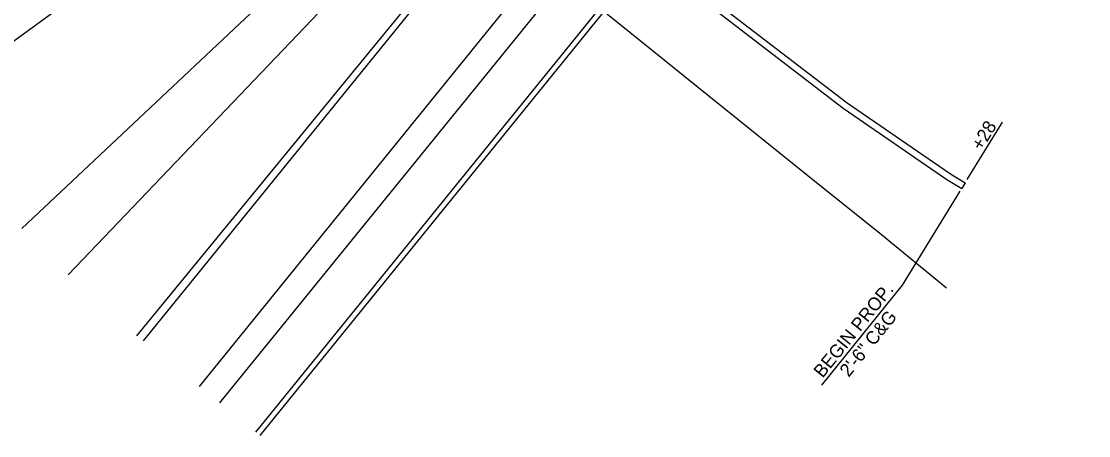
# Model space of a CAD drawing. Extents: x 1486489 to 1490134, y 497089 to 500876.
# Drawn here: x 1488844.3 to 1489168.8, y 498888.9 to 499014.9 of the extents above; entities that cross this region are included whole.
import ezdxf

# ---------------------------------------------------------------- set-up
doc = ezdxf.new("R2010")
doc.units = 0
for name, color, linetype in [('Old_Level_9', 7, 'Continuous'), ('Prop Text', 7, 'Continuous'), ('Scratch_Level_5', 7, 'Continuous'), ('Sheet Border Standard 30in CELL', 7, 'Continuous'), ('Sheet Cutting Line CELL', 7, 'Continuous'), ('Sheet Sticker Exception Certification CELL', 7, 'Continuous')]:
    doc.layers.add(name, color=color, linetype=linetype)

msp = doc.modelspace()

# ---------------------------------------------------------------- linework, layer by layer
at = {"layer": 'Old_Level_9'}
msp.add_lwpolyline([(1489125.56, 498933.79), (1489105.79, 498950), (1489083.46, 498967.96), (1489053.28, 498992.22), (1489018.86, 499019.95), (1488995.28, 499038.96), (1488972.75, 499057.15), (1488947.35, 499077.62), (1488919.48, 499100.08), (1488890.07, 499123.82), (1488841.68, 499162.79)], dxfattribs=at)
at = {"layer": 'Prop Text'}
for p, q in [((1489133.24, 499228.47), (1488881.33, 498917.76)), ((1488858.52, 498937.81), (1489134.65, 499227.2)), ((1489156.48, 499209.63), (1488904.57, 498898.92)), ((1489167.42, 499200.76), (1488915.51, 498890.05)), ((1488916.88, 498888.94), (1489168.79, 499199.65))]:
    msp.add_line(p, q, dxfattribs=at)
msp.add_lwpolyline([(1488898.42, 498903.91), (1488898.42, 498903.91), (1489150.33, 499214.62)], dxfattribs=at)
at = {"layer": 'Scratch_Level_5'}
msp.add_line((1489131.27, 498965.85), (1489130.23, 498964.14), dxfattribs=at)
msp.add_lwpolyline([(1489042.71, 499028.27), (1489054.46, 499018.99), (1489094.18, 498988.49), (1489125.68, 498966.85), (1489130.23, 498964.14)], dxfattribs=at)
at = {"layer": 'Sheet Border Standard 30in CELL'}
for p, q in [((1488879.44, 498919.3), (1489132.96, 499228.7)), ((1489135.79, 499226.06), (1488844.47, 498951.95)), ((1488814, 498988.85), (1489138.26, 499223.06))]:
    msp.add_line(p, q, dxfattribs=at)
at = {"layer": 'Sheet Cutting Line CELL'}
for p, q in [((1489131.85, 498966.79), (1489142.58, 498984.27)), ((1489112.19, 498934.75), (1489129.69, 498963.26)), ((1489087.62, 498904.28), (1489112.19, 498934.75))]:
    msp.add_line(p, q, dxfattribs=at)
at = {"layer": 'Sheet Sticker Exception Certification CELL'}
msp.add_lwpolyline([(1489043.97, 499029.82), (1489055.69, 499020.57), (1489095.36, 498990.11), (1489126.76, 498968.54), (1489131.27, 498965.85)], dxfattribs=at)

# ---------------------------------------------------------------- texts
at = {"layer": 'Sheet Cutting Line CELL'}
for s, rotation, p in [('+28', 58.4674, (1489136.22, 498975.36)), ('BEGIN PROP.', 51.1156, (1489087.92, 498906.25)), ('2\'-6" C&G', 51.1156, (1489095.85, 498906.52))]:
    msp.add_text(s, height=4, rotation=rotation, dxfattribs=at).set_placement(p)

doc.saveas('drawing.dxf')
